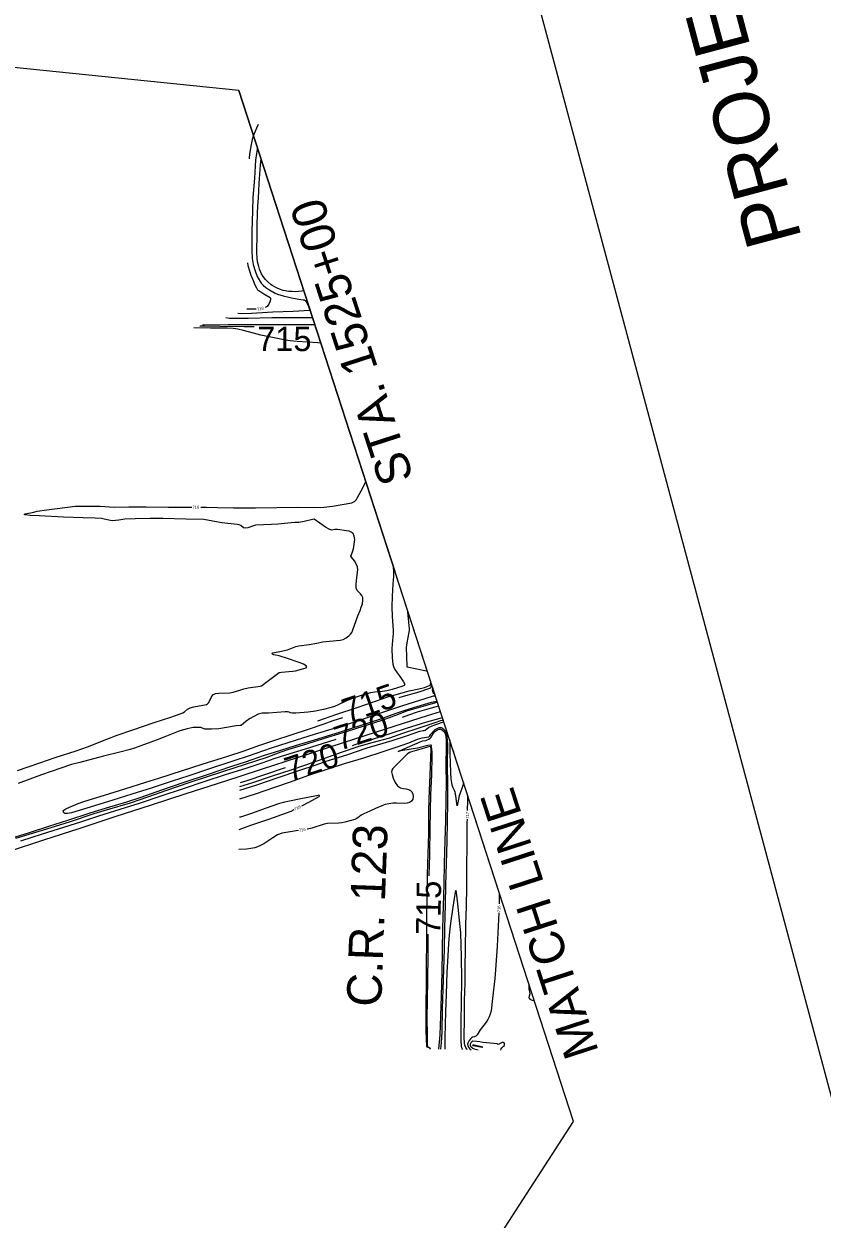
# Model space of a CAD drawing. Extents: x -361782338 to 28259792, y -263199453 to 8342113.
# Drawn here: x 1408556 to 1409637, y 577453 to 579070 of the extents above; entities that cross this region are included whole.
import ezdxf

# ---------------------------------------------------------------- set-up
doc = ezdxf.new("R2010")
doc.units = 0
for name, color, linetype in [('DT_X_Contour_Minor', 7, 'Continuous'), ('DT_X_Terrain_Ground_Line', 7, 'Continuous'), ('Level 14', 7, 'Continuous'), ('Level 19', 7, 'Continuous'), ('Level 40', 7, 'Continuous'), ('SC_Scratch1', 7, 'Continuous'), ('SH_Border', 7, 'Continuous'), ('SH_Data', 7, 'Continuous')]:
    doc.layers.add(name, color=color, linetype=linetype)

msp = doc.modelspace()

# ---------------------------------------------------------------- linework, layer by layer
at = {"layer": 'DT_X_Contour_Minor'}
for points in [[(1408873.4, 578934.2), (1408871.1, 578929.3), (1408866.5, 578918.6), (1408865.1, 578913.9), (1408863.7, 578907.5), (1408861.6, 578894.4), (1408861.2, 578888.8), (1408861.1, 578888)], [(1408872.3, 578903.2), (1408871, 578895), (1408869.9, 578886.2), (1408868.3, 578861.6), (1408866.3, 578835.6), (1408865.6, 578817.4), (1408864.9, 578789.4), (1408864.8, 578763.8), (1408865.4, 578753.1), (1408866.5, 578745.1), (1408869.1, 578736.2), (1408872.1, 578728.8), (1408877.4, 578719.7), (1408880.2, 578716.8), (1408883.9, 578713.8), (1408887.8, 578710.9), (1408896.4, 578706), (1408899.3, 578704.8), (1408907, 578702.6), (1408914.9, 578700.7), (1408918.6, 578699.7), (1408928.6, 578697.8), (1408934.4, 578696.9), (1408935.5, 578696.9), (1408936.2, 578696.7), (1408937.1, 578696), (1408938.3, 578694.3), (1408941.4, 578687.9), (1408943.4, 578682.5), (1408920.9, 578681.2), (1408893.4, 578680.2), (1408864.1, 578678.5), (1408851.1, 578678.3), (1408845.8, 578678.5)], [(1408935.2, 578709.5), (1408932.4, 578709), (1408923.4, 578708), (1408918.7, 578708.2), (1408914.8, 578708.5), (1408907.3, 578709.9), (1408902.1, 578711.5), (1408899.1, 578712.7), (1408892.3, 578716.4), (1408890.4, 578717.7), (1408886.2, 578721.3), (1408883.1, 578724.8), (1408880.3, 578728.6), (1408878, 578732.5), (1408875.3, 578738.6), (1408874.1, 578742.2), (1408872.6, 578748.4), (1408872, 578753), (1408871.6, 578761.3), (1408871.6, 578768.8), (1408871.9, 578779.4), (1408871.8, 578789.9), (1408872.1, 578798), (1408872.5, 578813.7), (1408873, 578824.6), (1408873.7, 578834.7), (1408874.7, 578854.4), (1408876.4, 578880), (1408877.2, 578888.1)], [(1408859, 578747), (1408859.5, 578743.7), (1408861.5, 578736.2), (1408863.3, 578730.4), (1408866.4, 578723.2), (1408869, 578717.3), (1408870.9, 578713.5), (1408872.6, 578710.8), (1408874, 578709.7), (1408881, 578705.2), (1408889.5, 578700.3), (1408889.9, 578699.4), (1408889.8, 578697.6), (1408889.2, 578694.6), (1408887.9, 578691.1), (1408885.3, 578688), (1408882.6, 578686.8)], [(1408829.7, 578673.3), (1408834.7, 578672.4), (1408837.9, 578672.1), (1408859.8, 578672.4), (1408892, 578673), (1408921.5, 578673.3), (1408946.9, 578673.4)], [(1408870.8, 578684.7), (1408867.3, 578684.4), (1408859.5, 578684.5), (1408858, 578684.5)], [(1408958.2, 578638.6), (1408954, 578639.1), (1408926.1, 578640.9), (1408916.6, 578641.5), (1408910.5, 578642.3), (1408895, 578645.5), (1408877.1, 578649.4), (1408871.8, 578650.5), (1408853.3, 578655.6), (1408845.9, 578657.3), (1408839.6, 578658.2), (1408831.3, 578658.6), (1408809, 578658.9), (1408786, 578659.1)], [(1408794.2, 578661.8), (1408800.6, 578661.7), (1408821.4, 578661.5), (1408854.2, 578661.2), (1408867.7, 578661.1)], [(1408950.2, 578663.3), (1408948, 578663.3), (1408921.4, 578663.3), (1408892.3, 578663.2), (1408860.1, 578663.1), (1408832.7, 578663.1), (1408800.5, 578662.9), (1408797.8, 578663)], [(1408950.2, 578660.4), (1408951.2, 578660.3)], [(1408795.6, 578416.4), (1408803.2, 578416.4), (1408818.3, 578416.3), (1408839.9, 578415.8), (1408869.5, 578415.7), (1408898.7, 578416.1), (1408926.1, 578416.5), (1408950, 578416.3), (1408962.3, 578416.7), (1408973.8, 578418), (1409000.3, 578422.3), (1409002.1, 578423.1), (1409003.9, 578424.4), (1409005.8, 578426.6), (1409008, 578429.7), (1409012.5, 578437.6), (1409016.6, 578445.5), (1409019, 578451.4), (1409019, 578451.5)], [(1409003.6, 578343.9), (1408999.8, 578348.9), (1408998.8, 578350.1), (1409000.7, 578354.9), (1409002.2, 578360.1), (1409003.5, 578366.5), (1409004, 578372.6), (1409003.4, 578377.3), (1409001.8, 578380.7), (1408999.4, 578382.8), (1408996.5, 578384), (1408993.1, 578384.7), (1408980.7, 578386.4), (1408977.2, 578386.5), (1408972.8, 578385.6), (1408969.6, 578386.6), (1408964.6, 578389.6), (1408949.2, 578400.1), (1408947.1, 578399.8), (1408935.7, 578397.3), (1408928.5, 578396), (1408923.5, 578395.7), (1408918, 578395.4), (1408900, 578393.4), (1408891.4, 578393.2), (1408869.9, 578392.3), (1408866.8, 578391.5), (1408859.4, 578388.7), (1408856.1, 578388), (1408853.5, 578388.7), (1408849.7, 578391.7), (1408847.6, 578392.7), (1408845, 578393.2), (1408824.3, 578395.4), (1408799.8, 578400), (1408775.2, 578400.2), (1408744.3, 578401), (1408726.9, 578401.2), (1408706.8, 578400.8), (1408692.7, 578400.1), (1408684.5, 578399), (1408680.2, 578398.3), (1408676.4, 578398.1), (1408673.3, 578398.3), (1408665, 578400.5), (1408661.4, 578401), (1408652.5, 578401.6), (1408636.4, 578402), (1408609.5, 578403.2), (1408577, 578404.6), (1408564.7, 578405.4), (1408557.7, 578406.3), (1408556.3, 578406.8), (1408557.8, 578407.4), (1408569.6, 578409.7), (1408574.1, 578410.9), (1408577.9, 578411.7), (1408583.6, 578412.6), (1408615.3, 578416.4), (1408625.3, 578417.7), (1408635.5, 578418), (1408659.3, 578417.7), (1408678.4, 578416.5), (1408698.2, 578417), (1408721.8, 578416.9), (1408751.7, 578416.4), (1408777.8, 578416.4), (1408783.6, 578416.4)], [(1408547.4, 578060), (1408577.5, 578070.5), (1408598.4, 578077.7), (1408626.9, 578087), (1408642, 578092.4), (1408668.2, 578102.6), (1408682.2, 578107.9), (1408703.5, 578115.2), (1408732.5, 578125.2), (1408755, 578132.4), (1408767.9, 578136.7), (1408771.2, 578138.1), (1408773.4, 578139.5), (1408777.7, 578143.1), (1408781.2, 578144.9), (1408786, 578146.3), (1408803.2, 578149.6), (1408804.7, 578150.5), (1408806.3, 578152.4), (1408809.5, 578159.2), (1408812.1, 578162.4), (1408815.7, 578164.2), (1408820.1, 578164.9), (1408834.9, 578165.4), (1408839.5, 578166.1), (1408844, 578167.4), (1408848.6, 578169.1), (1408853.8, 578170.7), (1408859.7, 578171.9), (1408876.2, 578174.3), (1408877.9, 578174.9), (1408881.9, 578177.7), (1408901.9, 578192.8), (1408904.7, 578193.4), (1408919.6, 578194.5), (1408924, 578195.2), (1408935.1, 578198.1), (1408938.1, 578199.2), (1408939.4, 578200.5), (1408938.2, 578202), (1408934.6, 578204), (1408928.8, 578206.4), (1408913, 578211.9), (1408901.8, 578215.3), (1408896.8, 578216.1), (1408894.6, 578216.7), (1408892.7, 578217.8), (1408892.2, 578218.4), (1408892.3, 578218.9), (1408893, 578219.4), (1408895.3, 578219.9), (1408902.8, 578221.3), (1408912.9, 578223.7), (1408917.7, 578225.3), (1408924.4, 578227.9), (1408928.3, 578228.7), (1408942.4, 578230.5), (1408952.7, 578232.4), (1408960.6, 578234.3), (1408969.8, 578235.4), (1408984.2, 578236.4), (1408988.6, 578237.5), (1408992.5, 578239.6), (1408995.9, 578242.2), (1408998.4, 578244.8), (1409000.1, 578247), (1409001.1, 578249.2), (1409008.4, 578269.7), (1409011.3, 578276.6), (1409013, 578281.1), (1409014.4, 578285.9), (1409015.2, 578290.5), (1409014.9, 578294.2), (1409013.6, 578297.1), (1409011.7, 578299.4), (1409009.6, 578301.4), (1409007.5, 578303.7), (1409006.1, 578307.1), (1409005.8, 578312), (1409006.3, 578317.7), (1409008.3, 578331.7), (1409007.7, 578335.6), (1409006, 578339.8), (1409003.6, 578343.9)], [(1409056, 578337.5), (1409056.6, 578327.4), (1409056.4, 578323), (1409055.5, 578312.2), (1409054.8, 578296.1), (1409054.5, 578281.7), (1409054.9, 578268.8), (1409056.3, 578250), (1409056, 578245.5), (1409054.7, 578231.3), (1409054.4, 578225), (1409054.9, 578212.7), (1409055.7, 578204.3), (1409056.5, 578201.1), (1409058.6, 578197), (1409066.6, 578185.4), (1409070.2, 578180.3), (1409071.9, 578177.2), (1409071.2, 578175.4), (1409067.9, 578173.9), (1409062, 578171.9), (1409054.7, 578169.7), (1409047.5, 578168), (1409041.4, 578167.2), (1409031.1, 578166.4), (1409025.6, 578165.4), (1409014, 578162.3), (1409003.1, 578158.6), (1408992.2, 578153.9), (1408981.5, 578149), (1408976.7, 578147), (1408972, 578145.3), (1408961.7, 578142.6), (1408950.8, 578140.6), (1408941, 578139.3), (1408924.2, 578137.7), (1408919.6, 578137.7), (1408917, 578138.2), (1408915.3, 578139.1), (1408913.2, 578139.7), (1408909.8, 578139.8), (1408887.3, 578138), (1408883.1, 578138), (1408878.7, 578137.6), (1408873.5, 578136.2), (1408867.6, 578133.4), (1408861.7, 578129.9), (1408856.8, 578126.5), (1408850.2, 578121.3), (1408849, 578121)], [(1409102.4, 578194.4), (1409101.1, 578194.7), (1409075.1, 578200.1), (1409075, 578201.6), (1409074.4, 578226.5), (1409075.3, 578233), (1409077.8, 578247.6), (1409078.1, 578249.6), (1409078.1, 578251.7), (1409077.4, 578260.7), (1409076.2, 578275), (1409076.2, 578275.1)], [(1408954, 578127.6), (1408979.9, 578136.3), (1409006.2, 578145.2), (1409033.6, 578154.5), (1409049.1, 578159.7), (1409068.1, 578165.3), (1409078, 578168), (1409091.1, 578170.9), (1409098.5, 578172.5), (1409103.1, 578174.1), (1409105.4, 578175.2), (1409106.1, 578175.8), (1409106.5, 578176.6), (1409107.1, 578179.9)], [(1409064.3, 578158.9), (1409070.1, 578160.8), (1409091.2, 578166.6), (1409105.6, 578171.5), (1409107, 578172.3), (1409107.6, 578173.3), (1409108.4, 578176)], [(1409109.7, 578172.2), (1409108.9, 578169), (1409109.5, 578166.9), (1409110.4, 578165.4), (1409111.9, 578164), (1409112.4, 578163.8)], [(1409113.3, 578160.9), (1409112.3, 578161), (1409110.1, 578160.6), (1409099.1, 578157.3), (1409068.8, 578147.8), (1409037.6, 578137.1), (1409028.6, 578134), (1409003.6, 578125.8), (1408977.8, 578117.6), (1408949.3, 578109), (1408924.6, 578101.2), (1408890.7, 578090.3), (1408859.7, 578079.6), (1408840.3, 578073.2), (1408807.2, 578062.5), (1408779.4, 578053.1), (1408756.8, 578045.6), (1408728.4, 578036.1), (1408702.4, 578028), (1408676.7, 578020.1), (1408645.8, 578010.7), (1408620.5, 578003), (1408615, 578001.9), (1408611.7, 578002), (1408610.2, 578003), (1408609.6, 578004.2), (1408609.4, 578005.3), (1408610.2, 578006.5), (1408612.9, 578008.2), (1408617.8, 578010.5), (1408629.8, 578015.5), (1408638.5, 578018.7), (1408665.3, 578027), (1408692.9, 578035.6), (1408721.4, 578044.4), (1408738.6, 578049.7), (1408770.7, 578060.2), (1408797.4, 578068.7), (1408832.2, 578079.7), (1408852.8, 578086.4), (1408875.4, 578094.3), (1408894.6, 578100.8), (1408919.3, 578108.8), (1408940, 578115.7), (1408962.5, 578123.4), (1408974.8, 578127.7), (1408987.9, 578132.1)], [(1408531.6, 577966.5), (1408563.5, 577976.3), (1408589.9, 577984.7), (1408615.4, 577992.8), (1408646, 578002.8), (1408672.4, 578010.9), (1408695.7, 578017.9), (1408714.7, 578024.3), (1408742.7, 578034.1), (1408773.3, 578044.4), (1408804.7, 578055), (1408837.6, 578065.9), (1408856.3, 578072.1), (1408882.1, 578080.8), (1408895.6, 578085.1), (1408924, 578093.9), (1408954.1, 578103), (1408984.6, 578112.5), (1409011.6, 578121.1), (1409038, 578129.6), (1409060.3, 578137.7), (1409070.9, 578141.5), (1409084, 578145.5), (1409108.2, 578152.6), (1409114.6, 578154.2), (1409115.5, 578154.3)], [(1409116.2, 578152), (1409113.3, 578151.6), (1409096.1, 578146.7), (1409074.4, 578140.3), (1409059.4, 578134.8), (1409039.5, 578127.6), (1409016.6, 578120.2), (1408992.7, 578112.7), (1408962.9, 578103.3), (1408938.9, 578096), (1408913.1, 578088.1), (1408903.8, 578084.9), (1408883.9, 578077.2), (1408855.8, 578068.2), (1408825.1, 578058.5), (1408804.2, 578051.6), (1408779.4, 578043.3), (1408749.3, 578033), (1408723.6, 578024.3), (1408700, 578016.1), (1408668.9, 578006.8), (1408650.8, 578001.4), (1408618.7, 577990.9), (1408604.3, 577986.3), (1408576.4, 577977.6), (1408544.9, 577968)], [(1409117.7, 578147.4), (1409107.8, 578144.5), (1409088.7, 578139), (1409077.1, 578135.2), (1409068.4, 578132)], [(1408848.6, 578033.6), (1408871.7, 578041), (1408900.3, 578050.8), (1408928.4, 578060.1), (1408951.7, 578068), (1408965.3, 578072.7), (1408993.5, 578081.6), (1409021.1, 578090.8), (1409034.8, 578095), (1409054.6, 578100.8), (1409074.3, 578107.2), (1409092.4, 578113.3), (1409096.4, 578114.1), (1409097.9, 578114.4), (1409099.3, 578114.9), (1409103.9, 578118.4), (1409108.8, 578120.5), (1409123.1, 578125.4), (1409124.1, 578125.3), (1409125.1, 578124.6)], [(1408848.7, 578038.4), (1408866, 578044), (1408891.6, 578052.5), (1408918.1, 578061.2), (1408936.6, 578067.5), (1408963.4, 578077.1), (1408986.2, 578084.9), (1409010.2, 578093), (1409027.9, 578098.1), (1409051.6, 578104.6), (1409069.3, 578110.5), (1409091.5, 578118.1), (1409112.8, 578125.2), (1409120.5, 578127.7), (1409123.4, 578128.2), (1409123.9, 578128.2)], [(1409001.2, 578094.2), (1409006, 578095.8), (1409028.1, 578102.5), (1409053.5, 578110.6), (1409074.4, 578117.6), (1409101.7, 578126.2), (1409119.8, 578130.9), (1409122.8, 578131.5)], [(1408849, 578121), (1408843.7, 578120.7), (1408820, 578116.8), (1408810.1, 578116.2), (1408803.4, 578116.1), (1408801.2, 578116.3), (1408795.6, 578118.2), (1408791.3, 578118.6), (1408785.1, 578118.3), (1408777, 578116.8), (1408767.2, 578113.8), (1408749.4, 578106.8), (1408736.5, 578101.8), (1408705.7, 578090.4), (1408699.9, 578088.6), (1408686, 578085.1), (1408664.1, 578079.8), (1408631.8, 578071.2), (1408620.7, 578068.2), (1408606.3, 578063.3), (1408579.8, 578054.2), (1408548.5, 578042.6)], [(1408848.4, 578021.7), (1408869.9, 578028.7), (1408896, 578037.5), (1408915.7, 578044.3), (1408942.1, 578054.1), (1408969.5, 578063.1), (1408990.3, 578069.5), (1409016.6, 578077.5), (1409042.5, 578085.9), (1409066.8, 578093.8), (1409077.5, 578097.8), (1409089.2, 578102.6), (1409095.5, 578104.4), (1409104.2, 578105.8), (1409105.7, 578107.2), (1409107.3, 578109.5), (1409110.8, 578113.5), (1409113.2, 578115.5), (1409115.9, 578117.1), (1409118.6, 578118.2), (1409120.9, 578118.4), (1409122.8, 578117.7), (1409125, 578115.5), (1409126.2, 578114), (1409126.8, 578112.6), (1409127.7, 578109.9), (1409128.6, 578105.9), (1409129.3, 578100.9), (1409129.5, 578095), (1409129.3, 578069.4), (1409129.8, 578039.3), (1409129.7, 578017.6), (1409129.2, 577990.1), (1409128.7, 577965.2), (1409127.7, 577934), (1409127.1, 577905.6), (1409126.5, 577879), (1409125.5, 577846.8), (1409125, 577818.4), (1409124.4, 577790.7), (1409123.5, 577764.3), (1409122.6, 577737.4), (1409121.8, 577705.9), (1409121, 577692.3), (1409120.3, 577683)], [(1409104.8, 577917.7), (1409104.9, 577922.6), (1409105.1, 577928.2), (1409105.7, 577950.2), (1409106.3, 577979.8), (1409106.6, 578006.5), (1409107.2, 578027.2), (1409108.3, 578054.7), (1409109, 578079.1), (1409108.8, 578085.5), (1409108.2, 578092), (1409107.9, 578093.7), (1409107.4, 578094.4), (1409106.5, 578094.5), (1409103.1, 578094), (1409088.9, 578090.6), (1409069.1, 578087.1), (1409062.7, 578085.8), (1409064, 578086.3), (1409068.8, 578088.4), (1409091.6, 578098.7), (1409096, 578100.2), (1409100.3, 578100.9), (1409102.2, 578101.6), (1409104.3, 578102.7), (1409106.1, 578104), (1409107.4, 578105.5), (1409110.6, 578110.7), (1409112.2, 578112.4), (1409114.1, 578114), (1409116.1, 578115.2), (1409118.2, 578116.1), (1409120, 578116.2), (1409121.4, 578115.7), (1409125, 578112.8), (1409125.8, 578111.7), (1409126.6, 578109.6), (1409127.3, 578106), (1409127.8, 578100.7), (1409127.8, 578093.5), (1409127.3, 578066.1), (1409127.7, 578043), (1409127.5, 578021.8), (1409126.9, 577992.6), (1409126.3, 577964.8), (1409125.4, 577934.9), (1409124.7, 577905.9), (1409124, 577877.1), (1409123.1, 577846.4), (1409122.7, 577817), (1409122.1, 577786.9), (1409121, 577755.4), (1409120, 577727.9), (1409119.2, 577702.4), (1409117.6, 577683)], [(1408551.8, 577965), (1408581.4, 577974.4), (1408602.8, 577981.1), (1408633, 577990.8), (1408657.7, 577998.9), (1408686.5, 578007.8), (1408714, 578016.6), (1408742, 578026), (1408772.1, 578035.9), (1408801.7, 578045.6), (1408829.2, 578054.6), (1408856.9, 578063.5), (1408880.2, 578071.1), (1408895, 578076.5), (1408910.6, 578081.4), (1408937.4, 578089.5), (1408968.9, 578099.5), (1408979.1, 578102.7)], [(1409106.3, 577683.1), (1409106.3, 577684.3), (1409102.1, 577686), (1409101.8, 577686.8), (1409101.5, 577688.5), (1409101.1, 577694.8), (1409100.8, 577710.5), (1409100.6, 577742.2), (1409101.1, 577771.9), (1409101.4, 577797.5), (1409101.7, 577828.4), (1409101.9, 577856.8), (1409102.3, 577890.2), (1409102.8, 577919.6), (1409103.7, 577947.7), (1409104.3, 577975), (1409104.5, 578004.9), (1409104.9, 578021.2), (1409106.3, 578054.3), (1409107.4, 578089.2), (1409107.1, 578091.2), (1409106.5, 578092.2), (1409105.7, 578092.5), (1409102.4, 578091.6), (1409087.4, 578087.3), (1409080.9, 578085.6), (1409078.1, 578084.4), (1409075.1, 578082.5), (1409072.2, 578079.7), (1409065.8, 578072.7), (1409055.8, 578063), (1409054.2, 578060.8), (1409053.9, 578058.3), (1409054.7, 578054.7), (1409056.3, 578049.7), (1409058.8, 578044.1), (1409062.1, 578039.5), (1409065.9, 578036.9), (1409070, 578035.8), (1409073.9, 578035.2), (1409077.1, 578034.5), (1409079.6, 578033.3), (1409081.5, 578031.2), (1409082.8, 578028.3), (1409083.4, 578024.9), (1409082.8, 578021.6), (1409081, 578018.9), (1409078.3, 578016.9), (1409075.2, 578015.8), (1409072.1, 578015.4), (1409060.5, 578016), (1409055.5, 578015.8), (1409050.3, 578015.1), (1409045.4, 578014), (1409040.7, 578012.4), (1409032.3, 578008.8), (1409024.6, 578005.1), (1409016.4, 578001.6), (1409012.9, 577999.8), (1409008.1, 577996), (1409006.2, 577994.6), (1409004.1, 577993.7), (1408990.8, 577990.4), (1408986.6, 577989.5), (1408982.6, 577989.1), (1408967.1, 577988.3), (1408962.6, 577987.4), (1408945.9, 577982.2), (1408939.9, 577981), (1408939.7, 577981)], [(1409132.3, 578102.5), (1409132.9, 578099.3), (1409133, 578094.9), (1409133, 578083.2), (1409133.7, 578057.3), (1409134.3, 578048.8), (1409135.5, 578040.6), (1409136.7, 578037.3), (1409138.7, 578033.5), (1409139.9, 578030.3), (1409140, 578030.2)], [(1409136.5, 578089.6), (1409136.8, 578087.7), (1409137.6, 578085.4), (1409138.1, 578084.7)], [(1408910, 578063.6), (1408881.7, 578054.2), (1408858.1, 578046.4), (1408848.8, 578043.4)], [(1409151.3, 578044), (1409150.7, 578041.4), (1409149, 578035.8), (1409147.2, 578031), (1409145.6, 578026), (1409143, 578012.6), (1409142.5, 578014.9), (1409140.8, 578026.2), (1409140, 578029.3)], [(1408932.6, 578012.6), (1408942, 578017.5), (1408955.9, 578025.2), (1408956.4, 578025.9), (1408956.2, 578026.4), (1408955.3, 578026.6), (1408952.4, 578026.1), (1408929, 578021.3), (1408907.1, 578016.7), (1408901, 578014.9), (1408884, 578009), (1408863, 578001.7), (1408849.2, 577997.2), (1408848, 577996.9)], [(1409156.8, 578006.2), (1409157.1, 578019.3), (1409157.2, 578025.7)], [(1408847.8, 577980.2), (1408863.2, 577986), (1408887.8, 577994.5), (1408911.6, 578002.9), (1408917.8, 578005.3), (1408921.9, 578007.2)], [(1409156.9, 577682.5), (1409156.1, 577683.1), (1409154.6, 577685.3), (1409153.2, 577688.5), (1409152.7, 577691.2), (1409152.4, 577698.7), (1409152.4, 577705.1), (1409152.8, 577718.1), (1409152.8, 577749), (1409153.5, 577772.5), (1409153.8, 577794.3), (1409153.9, 577818.4), (1409154.3, 577850.9), (1409155.3, 577876.7), (1409156, 577902.3), (1409156, 577932.4), (1409156.2, 577957.1), (1409156.5, 577989.9), (1409156.6, 577994.2)], [(1408927.9, 577979.2), (1408924.7, 577978.7), (1408916.5, 577977.1), (1408911.4, 577976.4), (1408905.7, 577975.2), (1408899.5, 577973), (1408893.2, 577969.3), (1408880.8, 577960.9), (1408874.8, 577957.8), (1408869, 577955.7), (1408863.2, 577954.5), (1408857.3, 577953.8), (1408847.3, 577953.1)], [(1409150, 577682.6), (1409149.8, 577683), (1409149.1, 577685), (1409148.7, 577687.6), (1409148.4, 577694.4), (1409148.4, 577699.3), (1409148.4, 577722.1), (1409148.5, 577745.4), (1409148.9, 577777.7), (1409148.5, 577807.6), (1409147.8, 577840.4), (1409146.6, 577853), (1409143.6, 577879.9), (1409141.9, 577895.1), (1409141, 577898), (1409139.9, 577895), (1409138.6, 577887.2), (1409136.9, 577875.2), (1409133.9, 577853.6), (1409131.8, 577837.4), (1409131, 577826), (1409129.5, 577801.4), (1409128.7, 577787.1), (1409127.7, 577757.3), (1409126.9, 577733.7), (1409126.2, 577699.4), (1409126, 577682.9)], [(1409199.8, 577894.6), (1409199.5, 577879.7)], [(1409199.2, 577867.7), (1409198.3, 577849.4), (1409196.9, 577822.6), (1409194.8, 577790.5), (1409193.8, 577778.9), (1409190.8, 577751.7), (1409188.8, 577734.8), (1409187.5, 577730.3), (1409186.1, 577726.8), (1409184.3, 577723.1), (1409181.9, 577719.5), (1409174.1, 577709.3), (1409169.7, 577702.3), (1409168, 577700.5), (1409166.4, 577699.6), (1409164, 577699.4), (1409163, 577699.3), (1409161.5, 577697.6), (1409159.1, 577694.6), (1409157.4, 577691.3), (1409157, 577689.7), (1409157.1, 577688.2), (1409158, 577685.8), (1409159.5, 577684.1), (1409161.8, 577682.4)], [(1409106.5, 577683.1), (1409106.4, 577684.5), (1409104.2, 577685.2), (1409103.3, 577685.8), (1409103, 577686.4), (1409102.6, 577689.9), (1409102.4, 577700.7), (1409102.1, 577726.9), (1409102.4, 577748), (1409103, 577779.2), (1409103.4, 577807.5), (1409103.6, 577835.7), (1409103.7, 577838.6)], [(1409247.2, 577748.6), (1409247.1, 577748.6), (1409244.7, 577749), (1409242.4, 577749.7), (1409240.8, 577751.1), (1409240.3, 577753.1), (1409240.6, 577755.3), (1409241.6, 577758.4), (1409240.4, 577764.7), (1409240.1, 577769.2), (1409240.2, 577769.9)], [(1409201.9, 577681.9), (1409202.2, 577683.6), (1409203.2, 577685.1), (1409205.5, 577687), (1409206.8, 577687.9), (1409207, 577689.2), (1409206.9, 577690.4), (1409206.5, 577691.6), (1409205.5, 577692.3), (1409203.8, 577692.1), (1409201.7, 577691.3), (1409199, 577689.7), (1409198.4, 577689.2), (1409197.6, 577690), (1409197.3, 577690.3), (1409177.7, 577692.1), (1409173.4, 577692.8), (1409169.4, 577693.5), (1409163.8, 577694), (1409162.7, 577693.2), (1409161.4, 577691.6), (1409160.5, 577689.9), (1409160.4, 577688.3), (1409160.8, 577687), (1409161.6, 577686.1), (1409164.1, 577684.4), (1409165.7, 577683.7), (1409171.1, 577682.3)], [(1409166.1, 577688.6), (1409163.8, 577688.7), (1409163.7, 577688.2), (1409164.1, 577688), (1409177.3, 577685.8), (1409177.7, 577685.9), (1409166.1, 577688.6)]]:
    msp.add_lwpolyline(points, dxfattribs=at)
at = {"layer": 'DT_X_Terrain_Ground_Line'}
for p in [(1408847.3, 578980.3), (1409300.2, 577585.4)]:
    msp.add_line(p, (1409058.5, 578329.9), dxfattribs=at)
at = {"layer": 'Level 14'}
msp.add_lwpolyline([(1409119.8, 578139.7), (1409102.2, 578134), (1409069.5, 578123.7), (1409019.3, 578107.4), (1408971.7, 578092.1), (1408926.3, 578077.5), (1408878.7, 578062.1), (1408847.3, 578051.8), (1408817.9, 578042.1), (1408775.5, 578028.5), (1408728.3, 578013.1), (1408679.4, 577997.4), (1408630.4, 577981.4), (1408582.6, 577965.9), (1408536.3, 577950.8)], dxfattribs=at)
at = {"layer": 'SC_Scratch1'}
msp.add_lwpolyline([(1400540.5, 577362.5), (1401030.8, 575831.8), (1401384.6, 574706.6), (1408690.6, 576642.8), (1409300.2, 577585.4), (1408847.3, 578980.3), (1403882.9, 579488), (1400534.4, 577997.6)], close=True, dxfattribs=at)
at = {"layer": 'SH_Border'}
msp.add_line((1410111.6, 575893.9), (1408481, 581979.2), dxfattribs=at)

# ---------------------------------------------------------------- texts
at = {"layer": 'DT_X_Terrain_Ground_Line'}
for s, p in [('STA. 1525+00', (1409084.2, 578456)), ('MATCH LINE', (1409334.8, 577679.8))]:
    msp.add_text(s, height=46.8, rotation=107.9864, dxfattribs=at).set_placement(p)
at = {"layer": 'Level 19'}
for s, height, rotation, p in [('719', 4, 11.1154, (1408872, 578682.2)), ('715', 33, 359.8118, (1408871.9, 578627.9)), ('716', 4, 0.1031, (1408784.3, 578414.4)), ('715', 33, 18.8847, (1408994, 578123.9)), ('720', 33, 17.8992, (1408983, 578086.6)), ('720', 33, 17.8706, (1408915.7, 578044.7)), ('716', 4, 27.4332, (1408923.4, 578005.6)), ('717', 4, 88.9746, (1409158.6, 577994.9)), ('716', 4, 8.623, (1408928.8, 577977.3)), ('715', 33, 88.9689, (1409119.9, 577837.3)), ('716', 4, 88.9803, (1409201.3, 577868.3))]:
    msp.add_text(s, height=height, rotation=rotation, dxfattribs=at).set_placement(p)
at = {"layer": 'Level 40'}
msp.add_text('C.R. 123', height=46.8, rotation=87.922, dxfattribs=at).set_placement((1409039.8, 577739.9))
at = {"layer": 'SH_Data'}
msp.add_text('PROJECT SITE PLAN', height=75, rotation=105, dxfattribs=at).set_placement((1409609.9, 578780.3))

doc.saveas('drawing.dxf')
